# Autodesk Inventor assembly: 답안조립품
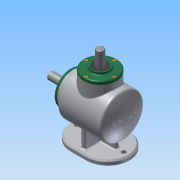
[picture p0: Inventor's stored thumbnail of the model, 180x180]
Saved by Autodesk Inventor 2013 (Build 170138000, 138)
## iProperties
Created: 2016-04
Part Number: 답안조립품
Document SubType Name: Assembly
Designer: Administrator
Author: Administrator
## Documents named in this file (14)
- C:\Users\Administrator\Desktop\460408V1009\답안조립품.iam
- C:\Users\Administrator\Desktop\460408V1009\1 본체.ipt
- C:\Users\Administrator\Desktop\460408V1009\메인 축.ipt
- 메인 축.ipt
- C:\Users\Administrator\Desktop\460408V1009\메인 베벨기어.ipt
- C:\Users\Administrator\Desktop\460408V1009\키 5x5.ipt
- C:\Users\Administrator\Desktop\460408V1009\커버.ipt
- C:\Users\Administrator\Desktop\460408V1009\베어링 6203.ipt
- C:\Users\Administrator\Desktop\460408V1009\오일실 17 32 8.ipt
- C:\Users\Administrator\Desktop\460408V1009\서브 축.ipt
- 서브 축.ipt
- C:\Users\Administrator\Desktop\460408V1009\서브 베벨기어.ipt
- C:\Users\Administrator\Desktop\460408V1009\키 4x4.ipt
- C:\Users\Administrator\Desktop\460408V1009\M4.ipt
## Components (9 placed, 2 different names)
1. 1 본체:1
2. M4:1
3. M4:3
4. M4:4
5. M4:5
6. M4:2
7. M4:6
8. M4:7
9. M4:8
